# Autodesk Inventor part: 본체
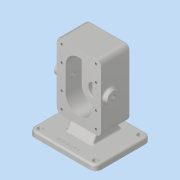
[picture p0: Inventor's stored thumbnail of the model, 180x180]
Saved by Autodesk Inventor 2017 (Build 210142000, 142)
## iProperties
Part Number: 본체
Material: 알루미늄 6061
Document SubType Name: Modeling
Designer: MRC
Density: 2.7 g/cm^3
Appearance: 알루미늄 - 평지
Mass: 1472.54 g
Surface Area: 818.394 cm^2
Volume: 545.387 cm^3
Author: MRC
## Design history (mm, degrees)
sketch "스케치1"
  geometry: L1 (-40, 60)-(40, 60); L2 (40, 60)-(40, -60); L3 (40, -60)-(-40, -60); L4 (-40, -60)-(-40, 60); L5 (-40, 60)-(40, -60); L6 (40, 60)-(-40, -60); 1 further point
  constraints: 12 end point, 2 midpoint, 2 parallel, 1 horizontal, 1 perpendicular
  dimensions: "d0" = 80 distance of L2.end L3.end; "d1" = 120 distance of L1.end L2.end
extrude "돌출1" new body sketch "스케치1" distance "d2" = 14; taper "d4" = 0 deg; dims "d3" = 39, "d5" = 0
sketch "스케치2"
  geometry: L1 (0, 22)-(0, -22); L2 (-24, 22)-(-24, -22); L3 (24, -22)-(24, 22); A1 r 24 centre (0, 22) between (24, 22) and (-24, 22); A2 r 24 centre (0, -22) between (-24, -22) and (24, -22); 2 further points
  constraints: 8 end point, 4 point on circle, 4 tangent, 2 centre point, 1 coincident, 1 midpoint, 1 parallel, 1 vertical
  dimensions: "d7" = 24 radius of A2; "d8" = 44 distance of L1.end L1.start
extrude "돌출2" cut sketch "스케치2" distance "d9" = 29; taper "d10" = 0 deg
sketch "스케치3"
  geometry: C1 r 12.5 at (0, 22); C2 r 12.5 at (0, -22); A1 r 24 centre (0, 22) between (24, 22) and (-24, 22) reference; A2 r 24 centre (0, -22) between (-24, -22) and (24, -22) reference; 1 further point
  constraints: 2 centre point, 2 concentric
  dimensions: "d11" = 25 diameter of C1; "d12" = 25 diameter of C2
extrude "돌출3" cut sketch "스케치3" distance "d13" = 15; taper "d14" = 0 deg
sketch "스케치4"
  geometry: C1 r 19 at (0, 22); 1 further point
  constraints: 1 centre point, 1 vertical alignment
  dimensions: "d15" = 38 diameter of C1; "d16" = 22 distance of C1.centre point (0, 0)
extrude "돌출4" join sketch "스케치4" distance "d17" = 17; taper "d18" = 0 deg
hole "구멍1" diameter "d21" = 17; stored, may be unused: countersink angle "d25" = 90 deg, drill point angle "d27" = 118 deg; dims "d19" = 10, "d20" = 10, "d22" = 6, "d23" = 28, "d24" = 7.3, "d26" = 8
sketch "스케치5"
  geometry: L1 (-40, -60)-(-40, 60) reference; L2 (-40, 0)-(40, 0); L3 (40, 60)-(40, -60) reference; L4 (-40, 0)-(-48, 0); L5 (-48, 0)-(-48, 11); L6 (-48, 11)-(-40, 11); L7 (-40, 11)-(-40, 0); 1 further point
  constraints: 10 end point, 2 midpoint, 2 parallel, 1 horizontal, 1 perpendicular
  dimensions: "d28" = 48 distance from line of point (0, 0) L5; "d29" = 22 diameter of L6 L4
revolve "회전1" sketch "스케치5" stored, may be unused: angle "d30" = 90 deg
hole "구멍2" diameter "d33" = 8.376; stored, may be unused: countersink angle "d37" = 90 deg, drill point angle "d39" = 118 deg; dims "d34" = 20, "d35" = 28, "d36" = 7.3, "d38" = 27.3, "d40" = 10, "d41" = 10
node "작업 평면1"
sketch "스케치6"
  geometry: L1 (59, 70)-(21, 70) reference; L2 (100, -30)-(-20, -30); L3 (-20, -30)-(-20, 70); L4 (-20, 70)-(100, 70); L5 (100, 70)-(100, -30); L6 (100, -30)-(-20, 70); L7 (-20, -30)-(100, 70); 3 further points
  constraints: 12 end point, 4 midpoint, 2 parallel, 1 horizontal, 1 perpendicular
  dimensions: "d43" = 120 distance of L3.end L4.end; "d44" = 100 distance of L2.end L3.end
extrude "돌출5" join sketch "스케치6" distance "d45" = 10; taper "d46" = 0 deg
sketch "스케치7"
  geometry: L1 (-46, 14)-(-46, -15) reference; L2 (-46, -15)-(-34.5, -15) reference; L3 (-34.5, -15)-(-34.5, -30) reference; L4 (-34.5, -30)-(-9.5, -30) reference; L5 (-9.5, -30)-(-9.5, -15) reference; L6 (-9.5, -15)-(9.5, -15) reference; L7 (9.5, -15)-(9.5, -30) reference; L8 (9.5, -30)-(13.5, -30) reference; L9 (13.5, -30)-(13.5, -48.7) reference; L10 (13.5, -48.7)-(8, -48.7) reference; L11 (8, -48.7)-(8, -56) reference; L12 (8, -56)-(3, -56) reference; L13 (3, -56)-(3, -39) reference; L14 (3, -39)-(-60, -39) reference; L15 (-60, -39)-(-60, 14) reference; L16 (-60, 14)-(-46, 14) reference; L17 (46, -15)-(46, 14) reference; L18 (46, 14)-(60, 14) reference; L19 (60, 14)-(60, -39) reference; L20 (60, -39)-(41, -39) reference; L21 (41, -39)-(41, -56) reference; L22 (41, -56)-(36, -56) reference; L23 (36, -56)-(36, -48.7) reference; L24 (36, -48.7)-(30.5, -48.7) reference; L25 (30.5, -48.7)-(30.5, -30) reference; L26 (30.5, -30)-(34.5, -30) reference; L27 (34.5, -30)-(34.5, -15) reference; L28 (34.5, -15)-(46, -15) reference; L29 (-90, 44)-(-80, 44) reference; L30 (-80, 44)-(-80, -56) reference; L31 (-80, -56)-(-90, -56) reference; L32 (-90, -56)-(-90, 44) reference; L33 (-80, -56)-(-80, 44) reference; L34 (-80, -39)-(-56.184, -25.25); L35 (-56.184, 0.25)-(-80, 14); L36 (-56.184, -25.25)-(-56.184, 0.25); 1 further point
  constraints: 6 end point, 2 point on line, 1 vertical
  dimensions: "d47" = 17 distance from line of L31 L34.start; "d49" = 60 deg angle of L30 L34; "d50" = 53 distance of L35.end L34.start; "d51" = 60 deg angle of L30 L35; "d52" = 25.4992 distance of L34.end L35.start
extrude "돌출6" join sketch "스케치7" stored distance "d53" = 48; taper "d54" = 0 deg
sketch "스케치8"
  geometry: A1 r 24 centre (0, 22) between (24, 22) and (-24, 22) reference; 5 further points
  constraints: 3 horizontal alignment, 2 vertical alignment
  dimensions: "d55" = 31 horizontal distance of A1.centre point (-31, 51); "d56" = 29 vertical distance of point (-31, 51) A1.centre; "d58" = 31 horizontal distance of point (31, 51) A1.centre
hole "구멍3" sketch "스케치8" at (-31, 51), (-31, 22), (31, 51), (31, 22) diameter "d59" = 4.134; stored, may be unused: countersink angle "d63" = 90 deg, drill point angle "d65" = 118 deg; dims "d60" = 10, "d61" = 28, "d62" = 7.3, "d64" = 12
fillet "모깎기1" dims "d66" = 10
chamfer "모따기1" distance "d67" = 0.7; stored, may be unused: second distance "d68" = 2, angle "d69" = 30 deg
fillet "모깎기2" dims "d70" = 0.5
fillet "모깎기3" dims "d71" = 9
fillet "모깎기4" dims "d72" = 3
fillet "모깎기5" dims "d73" = 3
fillet "모깎기6" dims "d74" = 3
chamfer "모따기2" distance "d75" = 1; stored, may be unused: second distance "d76" = 2, angle "d77" = 45 deg
chamfer "모따기3" distance "d78" = 1; stored, may be unused: second distance "d79" = 2, angle "d80" = 45 deg
sketch "스케치9"
  geometry: C1 r 4.5 at (-10, -20); C2 r 4.5 at (-10, 60); C3 r 4.5 at (90, 60); C4 r 4.5 at (90, -20); A1 r 7 centre (90, 60) between (97, 60) and (90, 67) reference; A2 r 7 centre (-10, 60) between (-10, 67) and (-17, 60) reference; A3 r 7 centre (-10, -20) between (-17, -20) and (-10, -27) reference; A4 r 7 centre (90, -20) between (90, -27) and (97, -20) reference; 1 further point
  constraints: 4 centre point, 4 coincident
  dimensions: "d81" = 9 diameter of C1; "d82" = 9 diameter of C2; "d83" = 9 diameter of C3; "d84" = 9 diameter of C4
extrude "돌출7" cut sketch "스케치9" stored distance "d85" = 48; taper "d86" = 0 deg
sketch "스케치10"
  geometry: L1 (-10, -30)-(90, -30) reference; L2 (-20, 60)-(-20, -20) reference; 2 further points
  constraints: 1 other
  dimensions: "d87" = 10 distance from line of point (40, -20) L1; "d88" = 60 distance from line of point (40, -20) L2
extrude "돌출8" join sketch "스케치10" distance "d89" = 0.5; taper "d90" = 0 deg
node "솔리드1"
mirror "미러1"
mirror "미러2"
node "절단 모서리 투영1"
